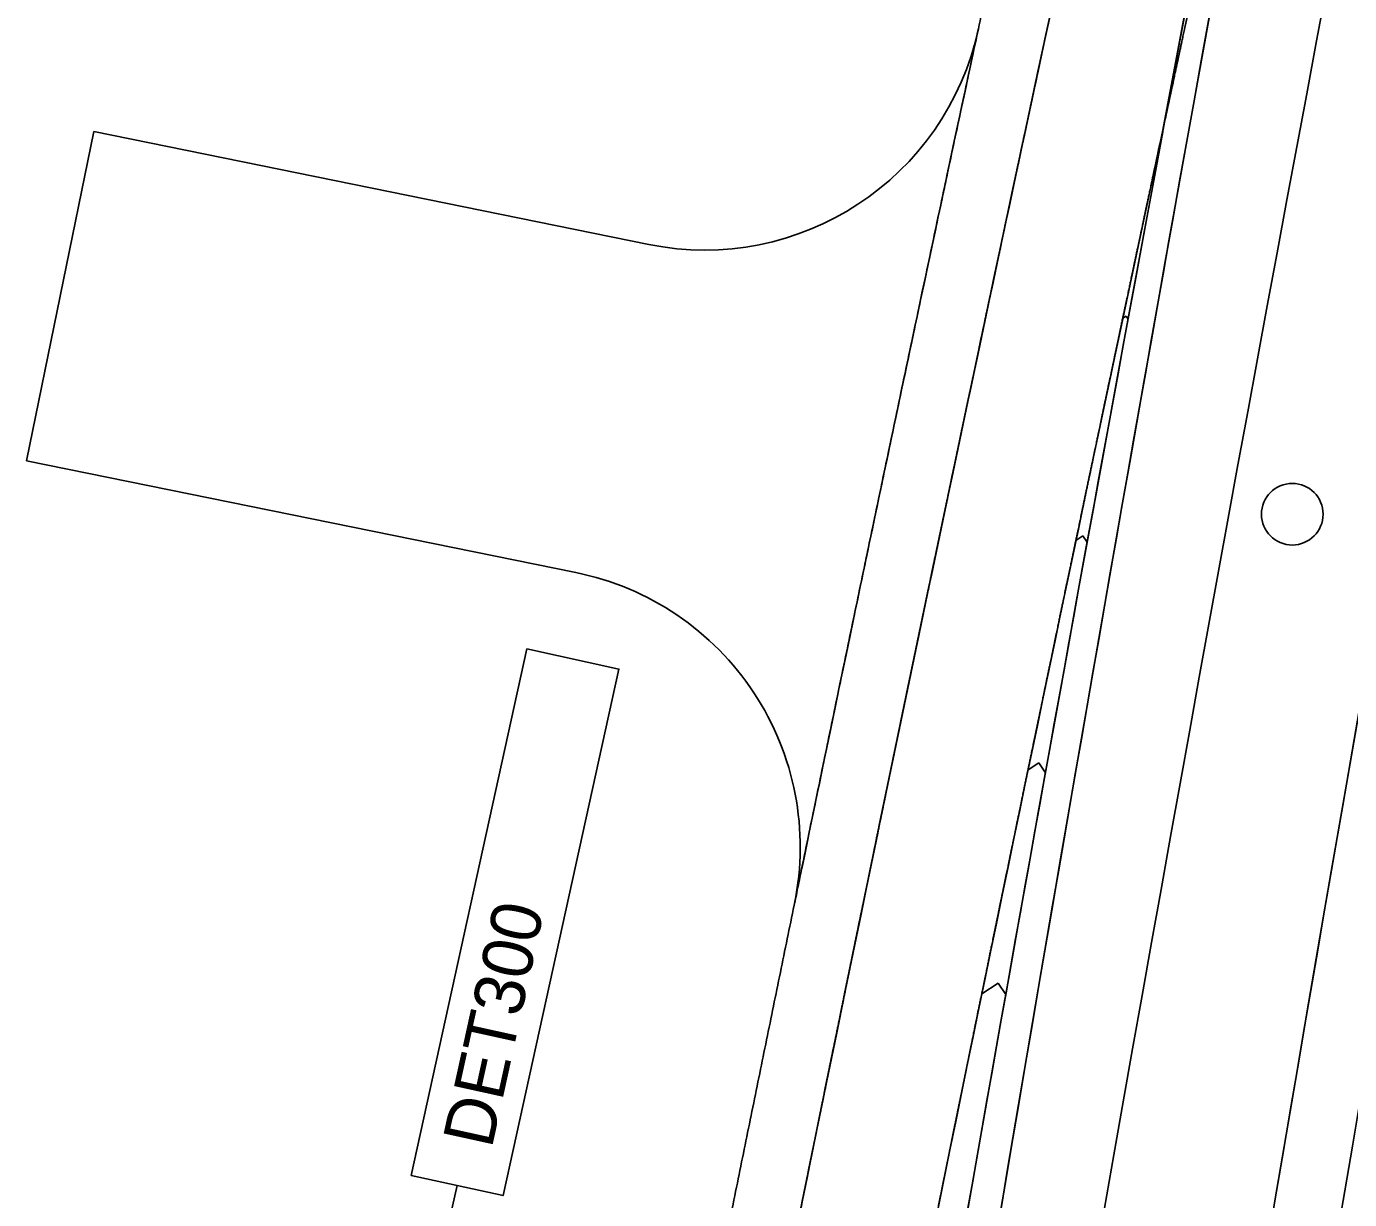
# Model space of a CAD drawing. Extents: x 14104283 to 14120882, y 8635219 to 8671666.
# Drawn here: x 14107941.7 to 14108059.8, y 8640504.3 to 8640609 of the extents above; entities that cross this region are included whole.
import ezdxf

# ---------------------------------------------------------------- set-up
doc = ezdxf.new("R2010")
doc.units = 0
for name, color, linetype in [('Cell', 7, 'Continuous'), ('dsnPaintPlaceBrokenLineWhite', 7, 'Continuous'), ('dsnPaintPlaceChannelizingLaneWhite', 7, 'Continuous'), ('dsnPaintPlaceEdgeLineRightWhite', 7, 'Continuous'), ('dsnShadingPaved', 7, 'Continuous'), ('dsnStgShadingPrevPav', 7, 'Continuous'), ('Text', 7, 'Continuous')]:
    doc.layers.add(name, color=color, linetype=linetype)

msp = doc.modelspace()

# ---------------------------------------------------------------- linework, layer by layer
at = {"layer": 'Cell'}
msp.add_circle((14108054.66, 8640565.46), 2.75, dxfattribs=at)
at = {"layer": 'dsnPaintPlaceBrokenLineWhite'}
msp.add_arc((14117394.14, 8638857.08), 9500, 167.610212, 171.325989, dxfattribs=at)
at = {"layer": 'dsnPaintPlaceChannelizingLaneWhite'}
for p, q in [((14108039.54, 8640582.95), (14108039.84, 8640583.14)), ((14108040.01, 8640582.88), (14108039.84, 8640583.14)), ((14108035.35, 8640563.12), (14108035.97, 8640563.52)), ((14108036.34, 8640562.96), (14108035.97, 8640563.52)), ((14108031.08, 8640542.65), (14108032.04, 8640543.28)), ((14108032.63, 8640542.38), (14108032.04, 8640543.28)), ((14108026.95, 8640522.65), (14108028.41, 8640523.61)), ((14108029.08, 8640522.59), (14108028.41, 8640523.61))]:
    msp.add_line(p, q, dxfattribs=at)
for centre, radius, start, end in [((14117394.14, 8638857.08), 9512, 169.444425, 171.325989), ((14117342.69, 8638609.63), 9510.13, 167.921867, 168.915877)]:
    msp.add_arc(centre, radius, start, end, dxfattribs=at)
at = {"layer": 'dsnPaintPlaceEdgeLineRightWhite'}
msp.add_arc((14117342.69, 8638609.63), 9522.13, 167.509575, 168.915877, dxfattribs=at)
at = {"layer": 'dsnShadingPaved'}
for centre, radius, start, end in [((14117394.14, 8638857.08), 9512, 167.610212, 171.325989), ((14117394.14, 8638857.08), 9500, 167.610212, 171.325989), ((14117502.5, 8638839.63), 9621.75, 168.048489, 169.460498), ((14117342.69, 8638609.63), 9522.13, 167.509575, 168.915877), ((14117342.69, 8638609.63), 9510.13, 167.921867, 168.915877)]:
    msp.add_arc(centre, radius, start, end, dxfattribs=at)
at = {"layer": 'dsnStgShadingPrevPav'}
for p, q in [((14107941.67, 8640570.22), (14107947.68, 8640599.61)), ((14107947.68, 8640599.61), (14107997.22, 8640589.54)), ((14107990.72, 8640560.25), (14107941.67, 8640570.22))]:
    msp.add_line(p, q, dxfattribs=at)
for centre, radius, start, end in [((14117407.82, 8638919.35), 9488, 167.610212, 172.222077), ((14117407.82, 8638919.35), 9482, 167.610212, 172.222077), ((14117407.82, 8638919.35), 9512, 169.413861, 172.222077), ((14117407.82, 8638919.35), 9512, 169.413861, 170.574102), ((14117407.82, 8638919.35), 9488, 169.413861, 172.222077), ((14108002.2, 8640614.04), 25, 258.5089, 347.8913), ((14107985.74, 8640535.75), 25, 348.3681, 78.5089)]:
    msp.add_arc(centre, radius, start, end, dxfattribs=at)
for points, degree in [([(14108040.07, 8640670.33), (14108039.11, 8640666.01), (14108035.79, 8640651.03), (14108029.85, 8640623.7), (14108025.19, 8640602.04), (14108020.26, 8640578.84), (14108015.47, 8640556.04), (14108010.72, 8640533.12), (14108006.03, 8640510.22), (14108001.39, 8640487.29), (14107996.81, 8640464.36), (14107992.28, 8640441.41), (14107987.82, 8640418.46), (14107983.4, 8640395.49), (14107979.05, 8640372.51), (14107974.75, 8640349.53), (14107970.51, 8640326.51), (14107966.33, 8640303.59), (14107962.15, 8640280.24), (14107958.29, 8640258.43), (14107953.48, 8640230.88), (14107950.9, 8640215.75), (14107950.15, 8640211.39)], 2), ([(14107956.07, 8640210.37), (14107957.38, 8640218.06), (14107960.02, 8640233.43), (14107964.04, 8640256.47), (14107968.11, 8640279.5), (14107972.24, 8640302.51), (14107976.42, 8640325.52), (14107980.66, 8640348.51), (14107984.96, 8640371.49), (14107989.32, 8640394.46), (14107993.73, 8640417.41), (14107998.19, 8640440.35), (14108002.71, 8640463.28), (14108007.29, 8640486.2), (14108011.92, 8640509.1), (14108016.61, 8640531.99), (14108021.36, 8640554.87), (14108026.16, 8640577.73), (14108031.01, 8640600.58), (14108035.93, 8640623.41), (14108040.89, 8640646.24), (14108044.25, 8640661.44), (14108045.92, 8640669.04)], 3), ([(14108032.74, 8640608.57), (14108032.82, 8640608.95), (14108032.9, 8640609.33), (14108032.98, 8640609.71)], 2), ([(14108045.28, 8640609.86), (14108045.2, 8640609.48), (14108045.12, 8640609.1), (14108045.03, 8640608.72)], 2), ([(14108045.03, 8640608.72), (14108045.12, 8640609.1), (14108045.2, 8640609.48), (14108045.28, 8640609.86)], 2), ([(14108026.65, 8640608.79), (14108026.14, 8640606.46), (14108024.06, 8640596.74), (14108020.26, 8640578.84), (14108015.47, 8640556.04), (14108012.14, 8640539.95), (14108010.4, 8640531.51), (14108010.23, 8640530.71)], 3), ([(14108032.49, 8640607.43), (14108032.57, 8640607.81), (14108032.65, 8640608.19), (14108032.74, 8640608.57)], 2), ([(14108045.03, 8640608.72), (14108044.71, 8640607.2), (14108044.38, 8640605.68), (14108044.06, 8640604.16)], 2), ([(14108044.06, 8640604.16), (14108044.38, 8640605.68), (14108044.71, 8640607.2), (14108045.03, 8640608.72)], 2), ([(14108032, 8640605.15), (14108032.16, 8640605.91), (14108032.33, 8640606.67), (14108032.49, 8640607.43)], 2), ([(14108031.27, 8640601.72), (14108031.51, 8640602.86), (14108031.76, 8640604), (14108032, 8640605.15)], 2), ([(14108044.06, 8640604.16), (14108043.81, 8640603.02), (14108043.57, 8640601.88), (14108043.32, 8640600.74)], 2), ([(14108043.32, 8640600.74), (14108043.57, 8640601.88), (14108043.81, 8640603.02), (14108044.06, 8640604.16)], 2), ([(14108031.02, 8640600.58), (14108031.1, 8640600.96), (14108031.18, 8640601.34), (14108031.27, 8640601.72)], 2), ([(14108030.78, 8640599.44), (14108030.86, 8640599.82), (14108030.94, 8640600.2), (14108031.02, 8640600.58)], 2), ([(14108043.32, 8640600.74), (14108043.24, 8640600.36), (14108043.16, 8640599.98), (14108043.08, 8640599.6)], 2), ([(14108043.08, 8640599.6), (14108043.16, 8640599.98), (14108043.24, 8640600.36), (14108043.32, 8640600.74)], 2), ([(14108030.05, 8640596.01), (14108030.29, 8640597.15), (14108030.53, 8640598.29), (14108030.78, 8640599.44)], 2), ([(14108043.08, 8640599.6), (14108043, 8640599.22), (14108042.92, 8640598.84), (14108042.83, 8640598.46)], 2), ([(14108042.83, 8640598.46), (14108042.92, 8640598.84), (14108043, 8640599.22), (14108043.08, 8640599.6)], 2), ([(14108042.83, 8640598.46), (14108042.59, 8640597.32), (14108042.35, 8640596.18), (14108042.1, 8640595.04)], 2), ([(14108042.1, 8640595.04), (14108042.35, 8640596.18), (14108042.59, 8640597.32), (14108042.83, 8640598.46)], 2), ([(14108029.8, 8640594.87), (14108029.88, 8640595.25), (14108029.97, 8640595.63), (14108030.05, 8640596.01)], 2), ([(14108029.32, 8640592.58), (14108029.48, 8640593.34), (14108029.64, 8640594.11), (14108029.8, 8640594.87)], 2), ([(14108042.1, 8640595.04), (14108041.78, 8640593.52), (14108041.45, 8640592), (14108041.13, 8640590.47)], 2), ([(14108041.13, 8640590.47), (14108041.45, 8640592), (14108041.78, 8640593.52), (14108042.1, 8640595.04)], 2), ([(14108029.07, 8640591.44), (14108029.15, 8640591.82), (14108029.24, 8640592.2), (14108029.32, 8640592.58)], 2), ([(14108028.59, 8640589.15), (14108028.75, 8640589.92), (14108028.91, 8640590.68), (14108029.07, 8640591.44)], 2), ([(14108041.13, 8640590.47), (14108041.05, 8640590.09), (14108040.97, 8640589.71), (14108040.89, 8640589.33)], 2), ([(14108040.89, 8640589.33), (14108040.97, 8640589.71), (14108041.05, 8640590.09), (14108041.13, 8640590.47)], 2), ([(14108028.1, 8640586.87), (14108028.26, 8640587.63), (14108028.43, 8640588.39), (14108028.59, 8640589.15)], 2), ([(14108040.89, 8640589.33), (14108040.4, 8640587.05), (14108039.92, 8640584.77), (14108039.43, 8640582.49)], 2), ([(14108039.43, 8640582.49), (14108039.92, 8640584.77), (14108040.4, 8640587.05), (14108040.89, 8640589.33)], 2), ([(14108027.86, 8640585.73), (14108027.94, 8640586.11), (14108028.02, 8640586.49), (14108028.1, 8640586.87)], 2), ([(14108027.37, 8640583.44), (14108027.54, 8640584.2), (14108027.7, 8640584.97), (14108027.86, 8640585.73)], 2), ([(14108026.65, 8640580.01), (14108026.89, 8640581.16), (14108027.13, 8640582.3), (14108027.37, 8640583.44)], 2), ([(14108039.43, 8640582.49), (14108039.35, 8640582.11), (14108039.27, 8640581.73), (14108039.19, 8640581.35)], 2), ([(14108039.19, 8640581.35), (14108039.27, 8640581.73), (14108039.35, 8640582.11), (14108039.43, 8640582.49)], 2), ([(14108038.95, 8640580.21), (14108038.71, 8640579.06), (14108038.47, 8640577.92), (14108038.22, 8640576.78)], 2), ([(14108038.22, 8640576.78), (14108038.47, 8640577.92), (14108038.71, 8640579.06), (14108038.95, 8640580.21)], 2), ([(14108039.19, 8640581.35), (14108039.11, 8640580.97), (14108039.03, 8640580.59), (14108038.95, 8640580.21)], 2), ([(14108038.95, 8640580.21), (14108039.03, 8640580.59), (14108039.11, 8640580.97), (14108039.19, 8640581.35)], 2), ([(14108026.41, 8640578.87), (14108026.49, 8640579.25), (14108026.57, 8640579.63), (14108026.65, 8640580.01)], 2), ([(14108026.17, 8640577.73), (14108026.25, 8640578.11), (14108026.33, 8640578.49), (14108026.41, 8640578.87)], 2), ([(14108025.68, 8640575.44), (14108025.84, 8640576.21), (14108026.01, 8640576.97), (14108026.17, 8640577.73)], 2), ([(14108038.22, 8640576.78), (14108038.14, 8640576.4), (14108038.06, 8640576.02), (14108037.98, 8640575.64)], 2), ([(14108037.98, 8640575.64), (14108038.06, 8640576.02), (14108038.14, 8640576.4), (14108038.22, 8640576.78)], 2), ([(14108037.98, 8640575.64), (14108037.5, 8640573.36), (14108037.02, 8640571.07), (14108036.54, 8640568.79)], 2), ([(14108036.54, 8640568.79), (14108037.02, 8640571.07), (14108037.5, 8640573.36), (14108037.98, 8640575.64)], 2), ([(14108025.2, 8640573.16), (14108025.28, 8640573.54), (14108025.36, 8640573.92), (14108025.44, 8640574.3)], 2), ([(14108025.44, 8640574.3), (14108025.52, 8640574.68), (14108025.6, 8640575.06), (14108025.68, 8640575.44)], 2), ([(14108024.72, 8640570.87), (14108024.88, 8640571.63), (14108025.04, 8640572.4), (14108025.2, 8640573.16)], 2), ([(14108024.48, 8640569.73), (14108024.56, 8640570.11), (14108024.64, 8640570.49), (14108024.72, 8640570.87)], 2), ([(14108023.76, 8640566.3), (14108024, 8640567.44), (14108024.24, 8640568.59), (14108024.48, 8640569.73)], 2), ([(14108036.54, 8640568.79), (14108035.98, 8640566.13), (14108035.42, 8640563.46), (14108034.86, 8640560.8)], 2), ([(14108034.86, 8640560.8), (14108035.42, 8640563.46), (14108035.98, 8640566.13), (14108036.54, 8640568.79)], 2), ([(14108023.52, 8640565.16), (14108023.6, 8640565.54), (14108023.68, 8640565.92), (14108023.76, 8640566.3)], 2), ([(14108023.04, 8640562.87), (14108023.2, 8640563.63), (14108023.36, 8640564.39), (14108023.52, 8640565.16)], 2), ([(14108022.08, 8640558.3), (14108022.4, 8640559.82), (14108022.72, 8640561.35), (14108023.04, 8640562.87)], 2), ([(14108034.86, 8640560.8), (14108034.78, 8640560.42), (14108034.7, 8640560.04), (14108034.62, 8640559.66)], 2), ([(14108034.62, 8640559.66), (14108034.7, 8640560.04), (14108034.78, 8640560.42), (14108034.86, 8640560.8)], 2), ([(14108034.62, 8640559.66), (14108034.22, 8640557.75), (14108033.82, 8640555.85), (14108033.43, 8640553.95)], 2), ([(14108033.43, 8640553.95), (14108033.82, 8640555.85), (14108034.22, 8640557.75), (14108034.62, 8640559.66)], 2), ([(14108021.84, 8640557.15), (14108021.92, 8640557.53), (14108022, 8640557.92), (14108022.08, 8640558.3)], 2), ([(14108021.6, 8640556.01), (14108021.68, 8640556.39), (14108021.76, 8640556.77), (14108021.84, 8640557.15)], 2), ([(14108021.37, 8640554.87), (14108021.45, 8640555.25), (14108021.52, 8640555.63), (14108021.6, 8640556.01)], 2), ([(14108020.17, 8640549.15), (14108020.57, 8640551.05), (14108020.97, 8640552.96), (14108021.37, 8640554.87)], 2), ([(14108033.43, 8640553.95), (14108033.35, 8640553.57), (14108033.27, 8640553.19), (14108033.19, 8640552.81)], 2), ([(14108033.19, 8640552.81), (14108033.27, 8640553.19), (14108033.35, 8640553.57), (14108033.43, 8640553.95)], 2), ([(14108033.19, 8640552.81), (14108032.87, 8640551.28), (14108032.55, 8640549.76), (14108032.24, 8640548.24)], 2), ([(14108032.24, 8640548.24), (14108032.55, 8640549.76), (14108032.87, 8640551.28), (14108033.19, 8640552.81)], 2), ([(14108019.94, 8640548), (14108020.02, 8640548.39), (14108020.09, 8640548.77), (14108020.17, 8640549.15)], 2), ([(14108019.7, 8640546.86), (14108019.78, 8640547.24), (14108019.86, 8640547.62), (14108019.94, 8640548)], 2), ([(14108032.24, 8640548.24), (14108032.16, 8640547.86), (14108032.08, 8640547.48), (14108032, 8640547.1)], 2), ([(14108032, 8640547.1), (14108032.08, 8640547.48), (14108032.16, 8640547.86), (14108032.24, 8640548.24)], 2), ([(14108018.99, 8640543.43), (14108019.22, 8640544.57), (14108019.46, 8640545.72), (14108019.7, 8640546.86)], 2), ([(14108032, 8640547.1), (14108031.84, 8640546.33), (14108031.68, 8640545.57), (14108031.52, 8640544.81)], 2), ([(14108031.52, 8640544.81), (14108031.68, 8640545.57), (14108031.84, 8640546.33), (14108032, 8640547.1)], 2), ([(14108031.52, 8640544.81), (14108031.21, 8640543.29), (14108030.89, 8640541.77), (14108030.57, 8640540.24)], 2), ([(14108030.57, 8640540.24), (14108030.89, 8640541.77), (14108031.21, 8640543.29), (14108031.52, 8640544.81)], 2), ([(14108018.75, 8640542.29), (14108018.83, 8640542.67), (14108018.91, 8640543.05), (14108018.99, 8640543.43)], 2), ([(14108018.28, 8640540), (14108018.43, 8640540.76), (14108018.59, 8640541.52), (14108018.75, 8640542.29)], 2), ([(14108030.57, 8640540.24), (14108030.42, 8640539.48), (14108030.26, 8640538.72), (14108030.1, 8640537.96)], 2), ([(14108030.1, 8640537.96), (14108030.26, 8640538.72), (14108030.42, 8640539.48), (14108030.57, 8640540.24)], 2), ([(14108017.33, 8640535.42), (14108017.64, 8640536.95), (14108017.96, 8640538.47), (14108018.28, 8640540)], 2), ([(14108030.1, 8640537.96), (14108029.71, 8640536.05), (14108029.31, 8640534.15), (14108028.92, 8640532.24)], 2), ([(14108028.92, 8640532.24), (14108029.31, 8640534.15), (14108029.71, 8640536.05), (14108030.1, 8640537.96)], 2), ([(14108016.86, 8640533.13), (14108017.01, 8640533.9), (14108017.17, 8640534.66), (14108017.33, 8640535.42)], 2), ([(14108016.62, 8640531.99), (14108016.7, 8640532.37), (14108016.78, 8640532.75), (14108016.86, 8640533.13)], 2), ([(14108016.39, 8640530.85), (14108016.46, 8640531.23), (14108016.54, 8640531.61), (14108016.62, 8640531.99)], 2), ([(14108028.92, 8640532.24), (14108028.76, 8640531.48), (14108028.6, 8640530.72), (14108028.45, 8640529.96)], 2), ([(14108028.45, 8640529.96), (14108028.6, 8640530.72), (14108028.76, 8640531.48), (14108028.92, 8640532.24)], 2), ([(14108014.97, 8640523.98), (14108015.44, 8640526.27), (14108015.91, 8640528.56), (14108016.39, 8640530.85)], 2), ([(14108028.45, 8640529.96), (14108028.37, 8640529.58), (14108028.29, 8640529.2), (14108028.21, 8640528.82)], 2), ([(14108028.21, 8640528.82), (14108028.29, 8640529.2), (14108028.37, 8640529.58), (14108028.45, 8640529.96)], 2), ([(14108028.21, 8640528.82), (14108027.82, 8640526.91), (14108027.43, 8640525.01), (14108027.04, 8640523.1)], 2), ([(14108027.04, 8640523.1), (14108027.43, 8640525.01), (14108027.82, 8640526.91), (14108028.21, 8640528.82)], 2), ([(14108014.74, 8640522.84), (14108014.82, 8640523.22), (14108014.9, 8640523.6), (14108014.97, 8640523.98)], 2), ([(14108013.33, 8640515.97), (14108013.8, 8640518.26), (14108014.27, 8640520.55), (14108014.74, 8640522.84)], 2), ([(14108027.04, 8640523.1), (14108026.72, 8640521.58), (14108026.41, 8640520.05), (14108026.1, 8640518.53)], 2), ([(14108026.1, 8640518.53), (14108026.41, 8640520.05), (14108026.72, 8640521.58), (14108027.04, 8640523.1)], 2), ([(14108026.1, 8640518.53), (14108026.02, 8640518.15), (14108025.94, 8640517.77), (14108025.86, 8640517.39)], 2), ([(14108025.86, 8640517.39), (14108025.94, 8640517.77), (14108026.02, 8640518.15), (14108026.1, 8640518.53)], 2), ([(14108025.86, 8640517.39), (14108025.71, 8640516.63), (14108025.55, 8640515.86), (14108025.4, 8640515.1)], 2), ([(14108025.4, 8640515.1), (14108025.55, 8640515.86), (14108025.71, 8640516.63), (14108025.86, 8640517.39)], 2), ([(14108012.4, 8640511.39), (14108012.71, 8640512.92), (14108013.02, 8640514.44), (14108013.33, 8640515.97)], 2), ([(14108025.4, 8640515.1), (14108025.24, 8640514.34), (14108025.09, 8640513.58), (14108024.93, 8640512.81)], 2), ([(14108024.93, 8640512.81), (14108025.09, 8640513.58), (14108025.24, 8640514.34), (14108025.4, 8640515.1)], 2), ([(14108024.93, 8640512.81), (14108024.7, 8640511.67), (14108024.46, 8640510.53), (14108024.23, 8640509.38)], 2), ([(14108024.23, 8640509.38), (14108024.46, 8640510.53), (14108024.7, 8640511.67), (14108024.93, 8640512.81)], 2), ([(14108012.17, 8640510.25), (14108012.24, 8640510.63), (14108012.32, 8640511.01), (14108012.4, 8640511.39)], 2), ([(14108011.93, 8640509.1), (14108012.01, 8640509.48), (14108012.09, 8640509.86), (14108012.17, 8640510.25)], 2), ([(14108024.23, 8640509.38), (14108024.15, 8640509), (14108024.07, 8640508.62), (14108024, 8640508.24)], 2), ([(14108024, 8640508.24), (14108024.07, 8640508.62), (14108024.15, 8640509), (14108024.23, 8640509.38)], 2), ([(14108011.47, 8640506.81), (14108011.62, 8640507.57), (14108011.78, 8640508.34), (14108011.93, 8640509.1)], 2), ([(14108024, 8640508.24), (14108023.92, 8640507.86), (14108023.84, 8640507.48), (14108023.76, 8640507.1)], 2), ([(14108023.76, 8640507.1), (14108023.84, 8640507.48), (14108023.92, 8640507.86), (14108024, 8640508.24)], 2), ([(14108023.76, 8640507.1), (14108023.69, 8640506.72), (14108023.61, 8640506.34), (14108023.53, 8640505.95)], 2), ([(14108023.53, 8640505.95), (14108023.61, 8640506.34), (14108023.69, 8640506.72), (14108023.76, 8640507.1)], 2), ([(14108010.77, 8640503.38), (14108011, 8640504.52), (14108011.23, 8640505.67), (14108011.47, 8640506.81)], 2), ([(14108023.53, 8640505.95), (14108023.45, 8640505.57), (14108023.38, 8640505.19), (14108023.3, 8640504.81)], 2), ([(14108023.3, 8640504.81), (14108023.38, 8640505.19), (14108023.45, 8640505.57), (14108023.53, 8640505.95)], 2), ([(14108023.3, 8640504.81), (14108023.22, 8640504.43), (14108023.14, 8640504.05), (14108023.07, 8640503.67)], 2), ([(14108023.07, 8640503.67), (14108023.14, 8640504.05), (14108023.22, 8640504.43), (14108023.3, 8640504.81)], 2)]:
    msp.add_open_spline(points, degree=degree, dxfattribs=at)
at = {"layer": 'Text'}
msp.add_lwpolyline([(14107976.02, 8640506.44), (14107986.34, 8640553.43), (14107994.55, 8640551.63), (14107984.22, 8640504.64)], close=True, dxfattribs=at)
msp.add_lwpolyline([(14107976.02, 8640506.44), (14107986.34, 8640553.43), (14107994.55, 8640551.63), (14107984.22, 8640504.64)], close=True, dxfattribs=at)
msp.add_lwpolyline([(14107980.12, 8640505.54), (14107976.97, 8640491.59), (14108028.32, 8640452.2)], dxfattribs=at)

# ---------------------------------------------------------------- texts
msp.add_text('DET300', height=4.484, rotation=77.6078, dxfattribs=at).set_placement((14107983.19, 8640508.75))

doc.saveas('drawing.dxf')
